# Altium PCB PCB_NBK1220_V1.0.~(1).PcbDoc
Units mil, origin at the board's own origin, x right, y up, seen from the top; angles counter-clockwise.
Board outline 2760.94 x 3491.25 mil, 2 copper layers (Top Layer, Bottom Layer), stack 21 mil thick; 40 components, 63 nets, 291 pads, 55 vias.
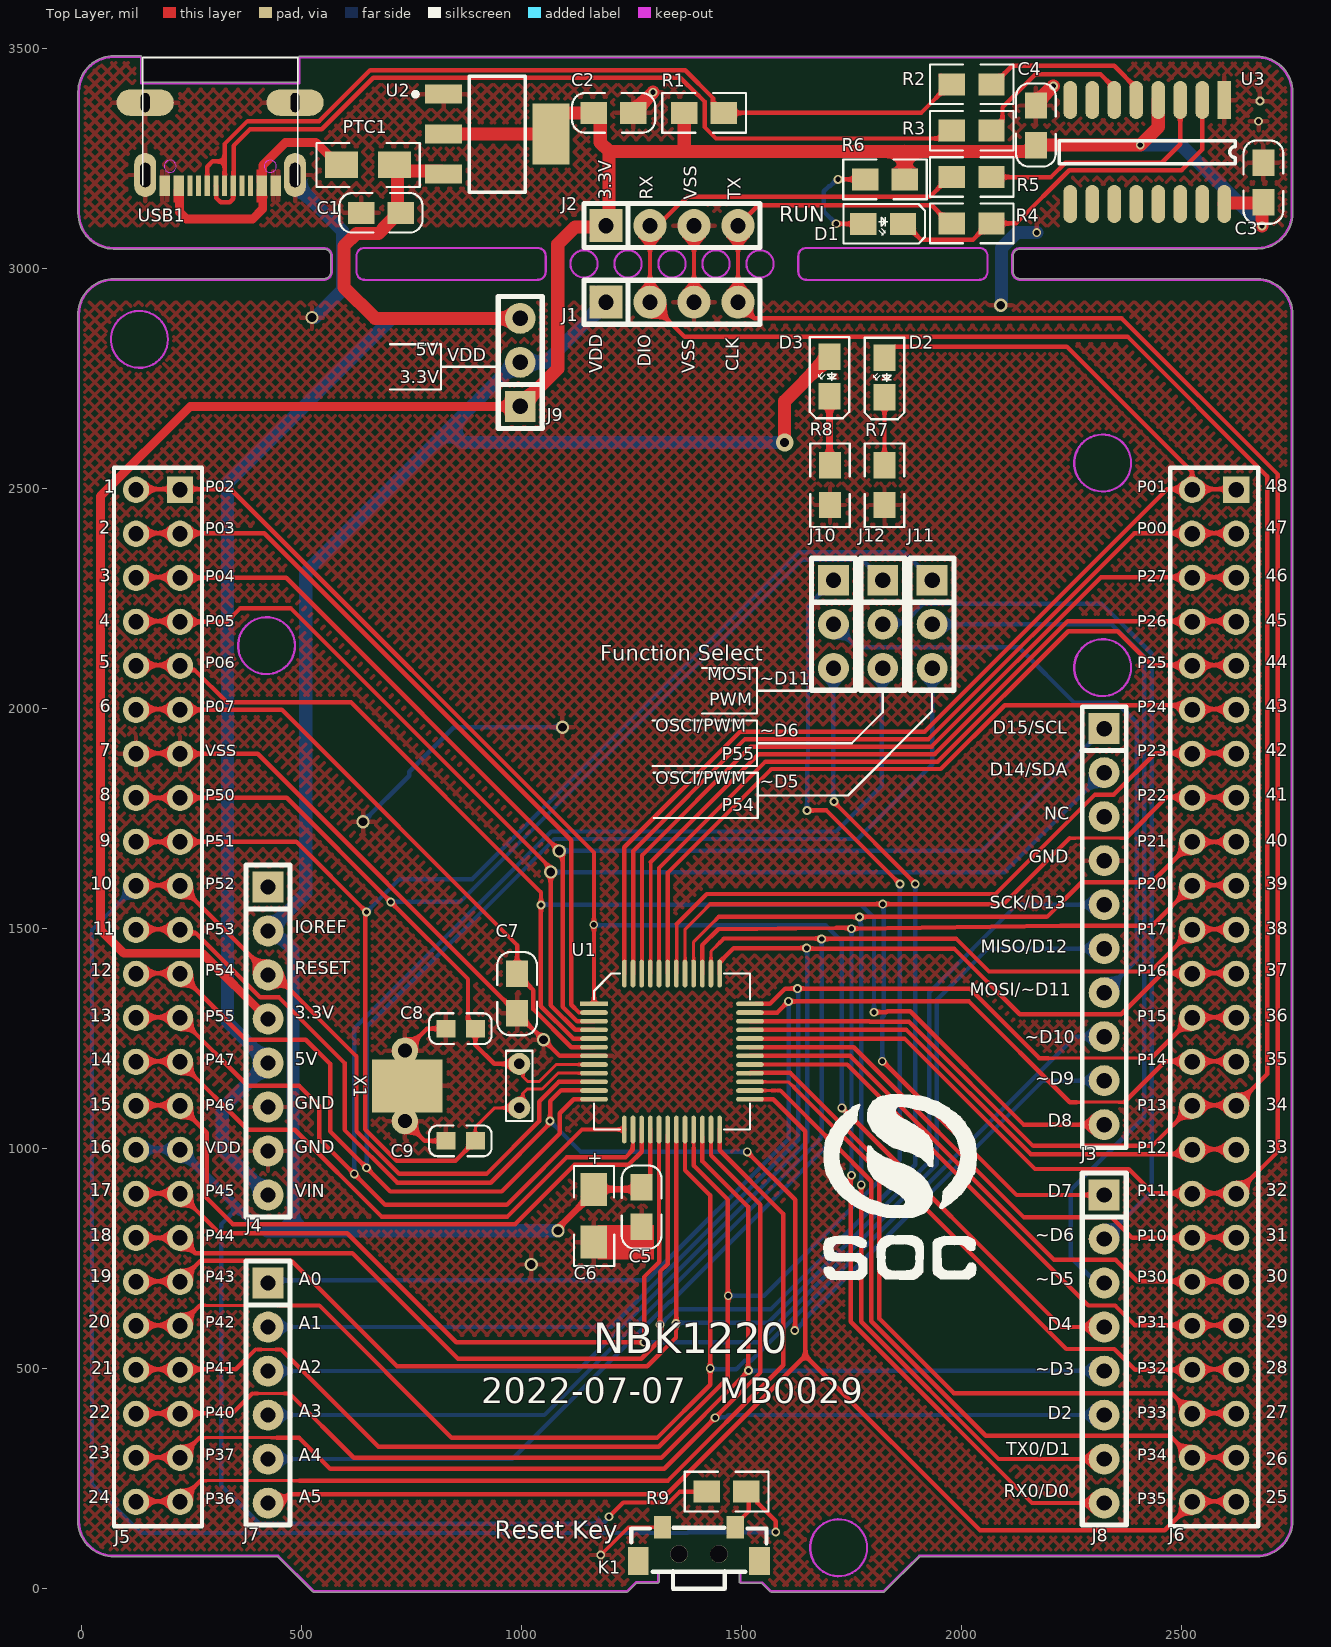
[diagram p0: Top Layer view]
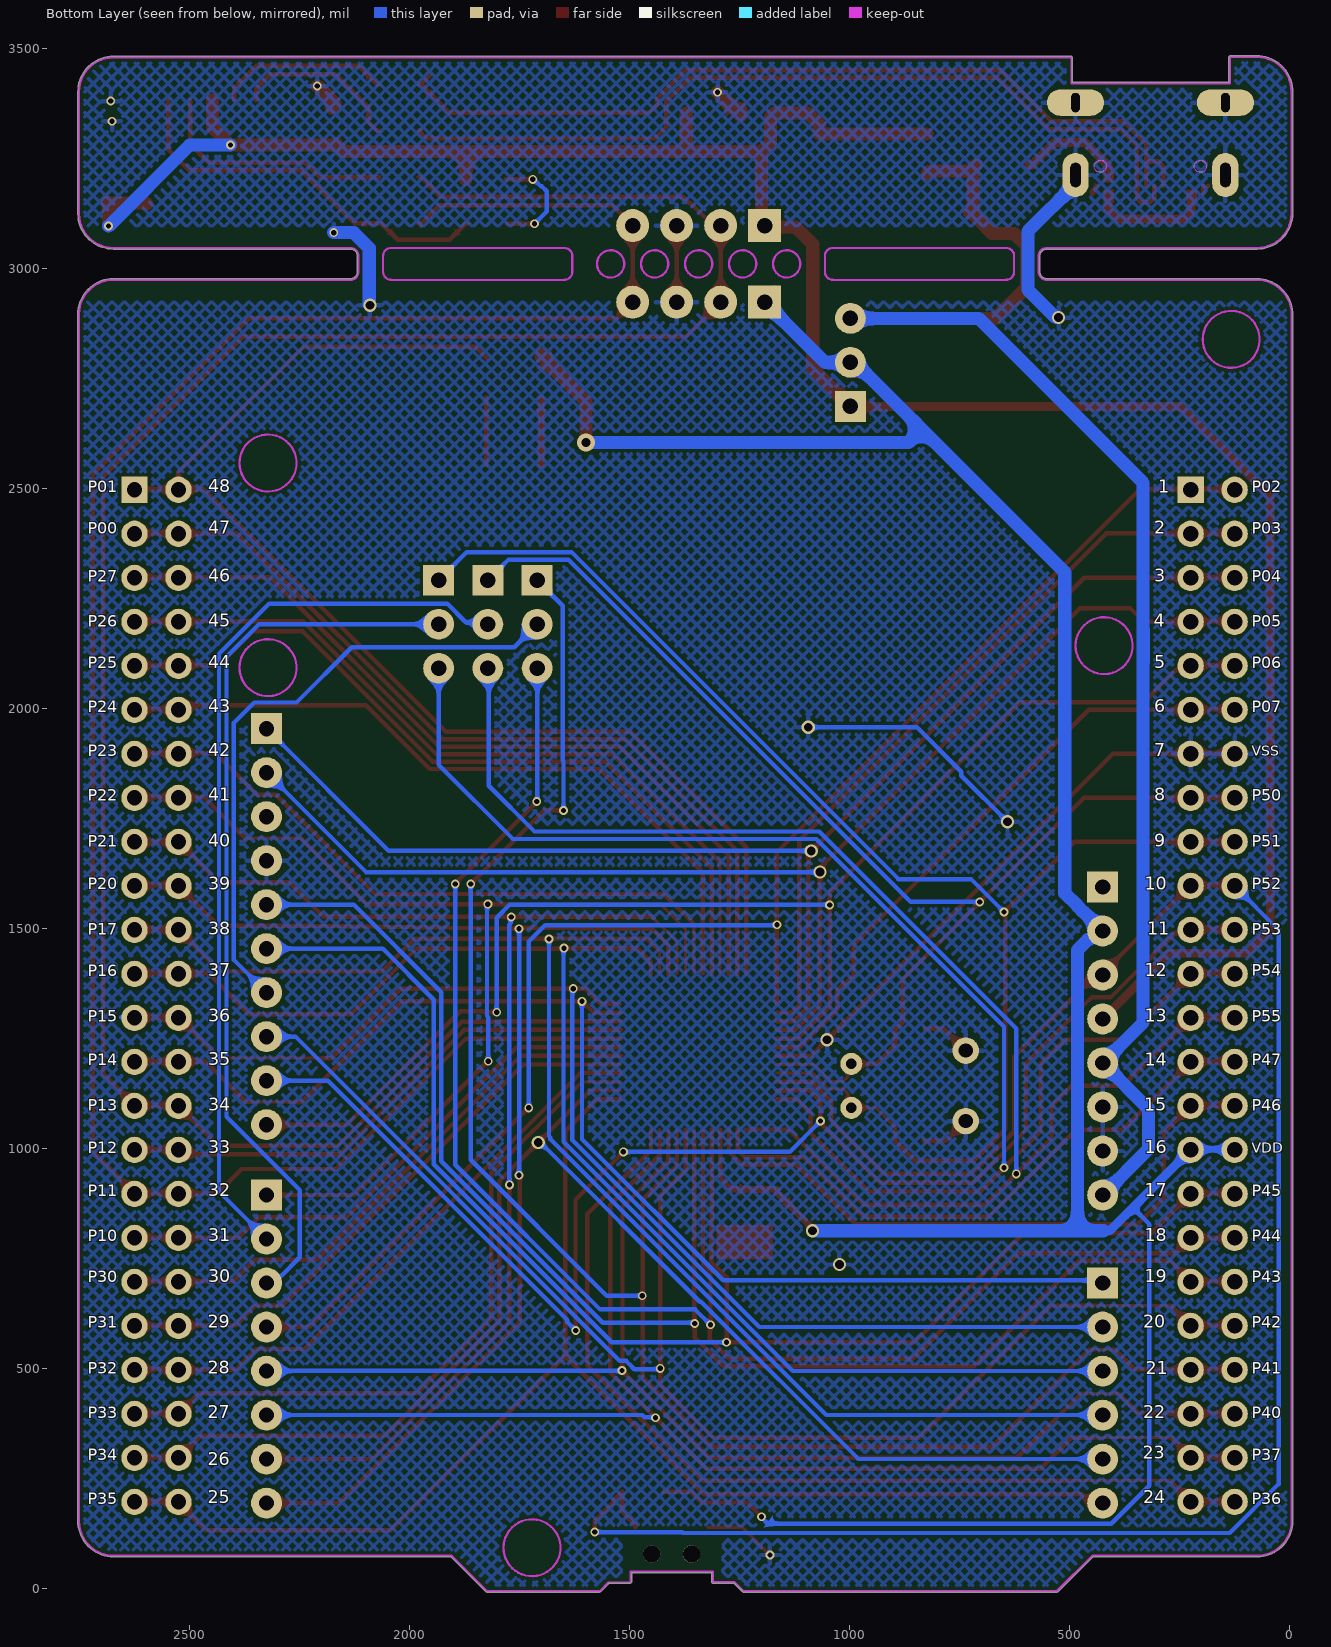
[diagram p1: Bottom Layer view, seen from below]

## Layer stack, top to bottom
Top Solder: solder mask 0.4, Solder Resist, Dk 3.5
Top Layer: signal copper 1.4
Dielectric 1: prepreg 2.8, PP-006, Dk 4.1
Dielectric1: dielectric 12.6, FR-4, Dk 4.8
Dielectric 2: prepreg 2.8, PP-006, Dk 4.1
Bottom Layer: signal copper 1.4
Bottom Solder: solder mask 0.4, Solder Resist, Dk 3.5

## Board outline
73.06,71.8 446.03,71.8 525.62,-7.79 527.39,-8.52 1240.4,-8.52 1242.18,-7.78 1261.44,11.48 1310,11.48 1312.51,14 1312.51,35.49 1494.49,35.49 1494.49,13.73 1497.36,11.21 1545.92,11.21 1565.18,-8.05 1568.1,-8.52 1823.45,-8.52 1825.23,-7.78 1904.81,71.8 2671.48,71.8 ccw(c2671.48,153.06) 2752.74,153.05 2752.74,2895.58 ccw(c2672.03,2895.58) 2672.58,2976.28 2671.95,2976.37 2133.15,2976.37 cw(c2133.15,2992) 2117.51,2992 2117.51,3028 cw(c2133.15,3028) 2133.15,3043.63 2671.95,3043.63 ccw(c2671.95,3124.34) 2752.66,3124.34 2752.66,3400.93 ccw(c2671.95,3400.93) 2671.95,3481.64 495,3481.64 492.49,3479.12 492.49,3422.52 137.51,3422.52 137.51,3480 134.78,3482.74 73.35,3482.74 ccw(c73.35,3401.48) -7.91,3401.48 -7.91,3124.89 ccw(c73.35,3124.89) 73.22,3043.63 550.95,3043.63 cw(c550.95,3028) 566.59,3028 566.59,2992 cw(c550.95,2992) 550.95,2976.37 550.06,2976.2 73.06,2976.2 ccw(c73.05,2894.94) -8.03,2900.23 -8.2,2899.31 -8.2,154 -8.2,153.05 ccw(c73.06,153.05)

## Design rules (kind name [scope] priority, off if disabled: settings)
Clearance Clearance_2 [(InComponent('U1') AND IsPad)] p1: gap=6 ignorepadtopadclearanceinfootprint=FALSE except(0: Arc-Hole Track-Hole SMDPad-Hole THPad-Hole Via-Hole Fill-Hole Poly-Hole Region-Hole Text-Hole)
Clearance Clearance_1 [All] p2: gap=6 ignorepadtopadclearanceinfootprint=FALSE except(0: Arc-Hole Track-Hole SMDPad-Hole THPad-Hole Via-Hole Fill-Hole Poly-Hole Region-Hole Text-Hole)
ComponentClearance [All] p1 off: gap=10 collisioncheckmode=3 verticalgap=10 showdistances=FALSE
Height [All] p1 off: minheight=0 maxheight=1000 prefheight=500
HoleSize [All] p1: absolutevalues=TRUE maxlimit=150 minlimit=1 maxpercent=80.000 minpercent=20.000
MinimumSolderMaskSliver [All] p1: minsoldermaskwidth=0
PolygonConnect [All] p1: connectstyle=Relief reliefconductorwidth=10 reliefentries=4 polygonreliefangle="90 Angle" airgapwidth=10
RoutingVias [All] p1: holewidth=28 width=50 viastyle="Through Hole" minholewidth=10 minwidth=20 maxholewidth=130 maxwidth=180
SilkToSilkClearance [All] p1 off: silktosilkclearance=0
SilkToSolderMaskClearance [IsPad] p1 off: minsilkscreentomaskgap=0 clearancetoexposedcopper=TRUE
SolderMaskExpansion [All] p1: expansion=4 istentingtop=FALSE
Width [All] p1: maxlimit=30 minlimit=5 preferedwidth=7
24 further rules are at their usual default settings.

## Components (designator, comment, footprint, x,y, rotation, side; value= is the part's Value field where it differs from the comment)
C1 "104" C0805 726,3126 r180 top
C2 "104" C0805 1164,3353 r0 top
C3 "104" C0805 2686,3150.2 r90 top
C4 "104" C0805 2169,3280 r90 top
C5 "104" C0805 1273,912 r270 top
C6 "10uF" A-3216 1164,907 r270 top
C7 "103" C0805 990,1397 r270 top
C8 "10pF" C0603 895,1272 r180 top
C9 "10pF" C0603 895,1017 r180 top
D1 "LED-Bule" LED0805 1822,3101 r0 top
D2 "LED-Bule" LED0805 1825,2752 r270 top
D3 "LED-Yellow" LED0805 1700,2754 r270 top
J1 "CON1*4" CON1*4(P=2.54) 1342,2923 r0 top
J2 "CON1*4" CON1*4(P=2.54) 1342,3097 r0 top
J3 "CON1*10" CON1*10(P=2.54) 2324,1504 r270 top
J4 "CON1*8" CON1*8(P=2.54) 424,1244 r270 top
J5 "CON2*24" CON2*24(P=2.54) 189,1346.5 r270 top
J6 "CON2*24" CON2*24(P=2.54) 2589,1346.5 r270 top
J7 "CON1*6" CON1*6(P=2.54) 424,444 r270 top
J8 "CON1*8" CON1*8(P=2.54) 2324,544 r270 top
J9 "CON1*3" CON1*3(P=2.54) 997,2786 r90 top
J10 "CON1*3" CON1*3(P=2.54) 1709,2191 r270 top
J11 "CON1*3" CON1*3(P=2.54) 1933,2191 r270 top
J12 "CON1*3" CON1*3(P=2.54) 1821,2191 r270 top
K1 "单路开关" SW-SMD_UK-B0246-SP25Y 1403.28,100.64 r180 top
PTC1 "0.5A 6V 自恢复保险丝" R1206 591,3235 r0 top
R1 "1.5K" R0805 1370,3353 r0 top
R2 "22R" R0805 1978,3418 r0 top
R3 "22R" R0805 1978,3312.67 r0 top
R4 "100R" R0805 2068,3102 r180 top
R5 "100R" R0805 2068,3207.33 r180 top
R6 "2.2K" R0805 1871,3202 r180 top
R7 "5.1K" R0805 1825,2552 r270 top
R8 "5.1K" R0805 1701,2552 r270 top
R9 "1.5K" R0805 1511,220 r180 top
U1 "SC95F8617B" LQFP-48(7X7) 1342,1220 r0 top
U2 "AMS1117-3.3V" SOT-223 945,3305 r270 top
U3 "CH340C" SOP16 2597,3382.22 r270 top
USB1 "TYPE-C" TYPE-C1 315.22,3282.01 r0 top
X1 "32.768K" 32768 995,1192 r270 top

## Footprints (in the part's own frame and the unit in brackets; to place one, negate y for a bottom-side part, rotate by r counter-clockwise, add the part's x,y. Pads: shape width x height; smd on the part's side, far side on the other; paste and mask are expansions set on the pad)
32768 [mil] "32.768KHZ"
  round 60 hole 32: 0(-30,-260) 0(130,-260)
  rect 120x160 smd: 0(50,-255)
  round 50 hole 24: 1(0,0) 2(100,0)
  silkscreen extent -30,-30 130,30
A-3216 [mil]
  rect 75x60 smd: 1(0,0) 2(120,0)
  silkscreen extent -53,-45 174,47
C0603 [mm]
  rect 1.1x1 smd: 1(0,0) 2(1.7,0)
  silkscreen extent -0.94,-0.89 2.67,0.89
C0805 [mil]
  rect 60x50 smd: 1(0,0) 2(90,0)
  silkscreen extent -49,-45 140,45
CON1*3(P=2.54) [mil]
  rect 70x70 hole 35: 1(-100,0)
  round 70 hole 35: 2(0,0) 3(100,0)
  silkscreen extent -150,-50 150,50
CON1*4(P=2.54) [mil]
  rect 75x75 hole 35: 1(-150,0)
  round 75 hole 35: 2(-50,0) 3(50,0) 4(150,0)
  silkscreen extent -200,-50 200,50
CON1*6(P=2.54) [mil]
  rect 70x70 hole 35: 1(-250,0)
  round 70 hole 35: 2(-150,0) 3(-50,0) 4(50,0) 5(150,0) 6(250,0)
  silkscreen extent -300,-50 300,50
CON1*8(P=2.54) [mil]
  rect 70x70 hole 35: 1(-350,0)
  round 70 hole 35: 2(-250,0) 3(-150,0) 4(-50,0) 5(50,0) 6(150,0) 7(250,0) 8(350,0)
  silkscreen extent -400,-50 400,50
CON1*10(P=2.54) [mil]
  rect 70x70 hole 35: 1(-450,0)
  round 70 hole 35: 2(-350,0) 3(-250,0) 4(-150,0) 5(-50,0) 6(50,0) 7(150,0) 8(250,0) 9(350,0) 10(450,0)
  silkscreen extent -500,-50 502,50
CON2*24(P=2.54) [mil]
  rect 60x60 hole 35: 1(-1150,35)
  round 60 hole 35: 2(-1150,-65) 3(-1050,35) 4(-1050,-65) 5(-950,35) 6(-950,-65) 7(-850,35) 8(-850,-65) 9(-750,35) 10(-750,-65) 11(-650,35) 12(-650,-65) 13(-550,35) 14(-550,-65) 15(-450,35) 16(-450,-65) 17(-350,35) 18(-350,-65) 19(-250,35) 20(-250,-65) 21(-150,35) 22(-150,-65) 23(-50,35) 24(-50,-65) 25(50,35) 26(50,-65) 27(150,35) 28(150,-65) 29(250,35) 30(250,-65) 31(350,35) 32(350,-65) 33(450,35) 34(450,-65) 35(550,35) 36(550,-65) 37(650,35) 38(650,-65) 39(750,35) 40(750,-65) 41(850,35) 42(850,-65) 43(950,35) 44(950,-65) 45(1050,35) 46(1050,-65) 47(1150,35) 48(1150,-65)
  silkscreen extent -1200,-115 1205,85
LED0805 [mil]
  rect 60x50 smd: 1(-45,0) 2(45,0)
  silkscreen extent -90,-45 95,45
LQFP-48(7X7) [mm]
  rect 1.6x0.27 smd: 1(-4.5,2.75)
  oval 1.6x0.27 smd: 2(-4.5,2.25) 3(-4.5,1.75) 4(-4.5,1.25) 5(-4.5,0.75) 6(-4.5,0.25) 7(-4.5,-0.25) 8(-4.5,-0.75) 9(-4.5,-1.25) 10(-4.5,-1.75) 11(-4.5,-2.25) 12(-4.5,-2.75) 25(4.5,-2.75) 26(4.5,-2.25) 27(4.5,-1.75) 28(4.5,-1.25) 29(4.5,-0.75) 30(4.5,-0.25) 31(4.5,0.25) 32(4.5,0.75) 33(4.5,1.25) 34(4.5,1.75) 35(4.5,2.25) 36(4.5,2.75)
  oval 0.27x1.6 smd: 13(-2.75,-4.5) 14(-2.25,-4.5) 15(-1.75,-4.5) 16(-1.25,-4.5) 17(-0.75,-4.5) 18(-0.25,-4.5) 19(0.25,-4.5) 20(0.75,-4.5) 21(1.25,-4.5) 22(1.75,-4.5) 23(2.25,-4.5) 24(2.75,-4.5) 37(2.75,4.5) 38(2.25,4.5) 39(1.75,4.5) 40(1.25,4.5) 41(0.75,4.5) 42(0.25,4.5) 43(-0.25,4.5) 44(-0.75,4.5) 45(-1.25,4.5) 46(-1.75,4.5) 47(-2.25,4.5) 48(-2.75,4.5)
  silkscreen extent -4.5,-4.5 4.5,4.5
R0805 [mil]
  rect 60x50 smd: 1(0,0) 2(90,0)
  silkscreen extent -50,-45 140,45
R1206 [mil]
  rect 75x60 smd: 1(0,0) 2(120,0)
  silkscreen extent -57,-50 178,50
SOP16 [mm]
  rect 2.2x0.8 smd: 1(0,0)
  oval 2.2x0.8 smd: 2(0,-1.27) 3(0,-2.54) 4(0,-3.81) 5(0,-5.08) 6(0,-6.35) 7(0,-7.62) 8(0,-8.89) 9(6,-8.89) 10(6,-7.62) 11(6,-6.35) 12(6,-5.08) 13(6,-3.81) 14(6,-2.54) 15(6,-1.27) 16(6,0)
  silkscreen extent 2.33,-9.53 3.67,0.64
SOT-223 [mm]
  rect 1.1x2.15 smd: 1(-2.3,-3.1) 2(0,-3.1) 3(2.3,-3.1)
  rect 3.5x2.15 smd: 2(0,3.1)
  silkscreen extent -3.35,-4.85 3.35,1.63
SW-SMD_UK-B0246-SP25Y [mm]
  rect 1x1.3 smd: 1(2.1,-0.975) 2(-2.1,-0.975)
  rect 1.2x1.6 smd: 3(-3.5,0.975) 4(3.5,0.975)
  round 1 hole 1 unplated: ""(-1.15,0.575) ""(1.15,0.575)
  silkscreen extent -3.9,-0.95 3.9,2.57
TYPE-C1 [mm]
  oval 3.302x1.524 / inner oval 1.27x2.54 / far side oval 3.302x1.524 hole 0.5 slot 1.1 at 90 deg: 1(-4.325,2.4) 3(4.325,2.4)
  oval 1.27x2.54 / inner oval 1.27x2.54 / far side oval 1.524x2.54 hole 0.6 slot 1.4 at 90 deg: 2(-4.325,-1.78) 4(4.325,-1.78)
  rect 0.3x1.2 smd: A1(3.355,-2.4) A4(2.555,-2.4) A5(1.255,-2.4) A6(0.255,-2.4) A7(-0.245,-2.4) A8(-1.245,-2.4) A9(-2.545,-2.4) A12(-3.345,-2.4) B1(-3.045,-2.4) B4(-2.245,-2.4) B5(-1.745,-2.4) B6(-0.745,-2.4) B7(0.755,-2.4) B8(1.755,-2.4) B9(2.255,-2.4) B12(3.055,-2.4)
  Keep-Out Layer circle w0.05: c-2.885,-1.28 r0.35
  Keep-Out Layer circle w0.05: c2.895,-1.28 r0.35
  silkscreen extent -4.47,-2.35 4.48,5

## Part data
C1 C2 C3 C4 C5 C7 C8 C9: library part CAP1, "贴片电容"
C6: library part T-A/4.7uF/16V
D1 D2: library part LED-CP, "蓝色"
D3: library part LED-CP, "黄色"
K1: library part KEY-6
PTC1: library part PTC-MZ11-06A200-400RM, "6V 500mA PTC自恢复保险丝"
R1 R2 R3 R4 R5 R6 R7 R8 R9: library part R0805
U1: "电压:2.0V-5.5V;ROM:128KB;RAM:内部256B+外部8KB+ PWM&LCD 80B;32/16/8/4MHz"
U2: library part LDO-SPX1117M3, "LDO；1A；SOT-223-3"
USB1: library part TYPE-C1, "Type-c母座16pin 快充闪充usb3.0沉板母座连接器"
X1: library part CRYSTAL

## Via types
v1: diameter 20, hole 12, Top Layer to Bottom Layer, 44 vias
v2: diameter 30, hole 20, Top Layer to Bottom Layer, tented both sides, 8 vias
v3: diameter 30, hole 20, Top Layer to Bottom Layer, 2 vias
v4: diameter 40, hole 20, Top Layer to Bottom Layer, tented both sides, 1 vias

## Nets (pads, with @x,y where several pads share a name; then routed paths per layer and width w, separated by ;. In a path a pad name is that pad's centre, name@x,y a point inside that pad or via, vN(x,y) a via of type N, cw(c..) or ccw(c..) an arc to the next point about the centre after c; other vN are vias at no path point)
3.3V: C2.1 C3.1 C4.1 J2.1 J4.4 J9.1 R1.1 R6.1 U2.2 U3.4 U3.16 | length 5682
  Top Layer w20: J4.4 274.5,1443.5 96.5,1443.5 43,1497 43,2481.97 247.03,2686 J9.1
  Top Layer w30: U2.2@822.95,3305 1067.05,3305 1067.05,3325.68 1094.37,3353 C2.1 1169,3353 1179,3343 1179,3285.67 1199,3265.67 ; J9.1 1082.5,2771.5 1082.5,3054.5 1122,3094 1189,3094 J2.1 1199,3104 1199,3265.67 ; R1.1 1370,3265.67 ; R6.1 1871,3265.67 ; C4.1@2165,3280 v1(2406,3280) 2447,3321 U3.4 ; C4.1@2165,3282 2148.67,3265.67 1871,3265.67 ; U3.16 2597,3147.41 2597.69,3148.1 C3.1@2683.9,3148.1 ; v1(2683,3096) 2683,3147.2 C3.1@2683.9,3148.1 ; C3.1 C3.1@2683.9,3148.1 ; 1199,3265.67 1370,3265.67 ; 1370,3265.67 1871,3265.67
  Bottom Layer w30: J2.1@1169.5,3074.5 J2.1 ; v1(2406,3280) 2499,3280 v1(2683,3096)
5V: C1.1 J4.5 J4.8 J9.3 PTC1.2 U2.3 | length 3483.2
  Top Layer w30: U2.3 816.3,3221.1 724.9,3221.1 PTC1.2 718.5,3227.5 718.5,3133.5 C1.1 721,3126 688,3093 688,3091.89 675.06,3078.94 624.94,3078.94 596.6,3050.6 596.6,2957 667.6,2886 J9.3
  Bottom Layer w30: J4.8 320,998 320,1090 J4.5 332,1286 332,2104.95 331.48,2105.47 331.48,2179.38 332,2179.9 332,2512.33 705.67,2886 J9.3
A0: J6.27 J6.28 J7.1 U1.35 | length 2886.2
  Top Layer w7: 2262,1105 2369.87,1105
  Top Layer w10: U1.35 1581.06,1308.58 1606.48,1334 2016.89,1334 2245.89,1105 2262,1105 ; 2369.87,1105 2462.87,1198 2524,1198 J6.27@2624,1198
  Bottom Layer w10: J7.1 430,700 1286,700 1607,1021 v1(1607,1334) ; J6.27@2624,1192 J6.27@2624,1198
A1: J6.25 J6.26 J7.2 U1.36 | length 2979.1
  Top Layer w7: U1.36 U1.36@1533,1328.27 ; 2197,1205 2431,1205
  Top Layer w10: U1.36@1533,1328.27 1564.27,1328.27 1599,1363 v1(1627,1363) 2019,1363 2177,1205 2197,1205 ; 2431,1205 2524,1298 J6.25@2624,1298
  Bottom Layer w10: J7.2 1204.04,594 1629,1018.96 1629,1343.11 1628.91,1343.2 1628.91,1361.09 v1(1627,1363) ; J6.25@2624,1298 2654,1298
A2: J6.23 J6.24 J7.3 U1.37 | length 3208.4
  Top Layer w10: J7.3 J7.3@433.77,484.23 ; U1.37 1450.27,1423.35 1481.92,1455 v1(1648,1455) ; v1@1648,1454 1983,1454 2132,1305 2363,1305 2456,1398 J6.23@2624,1398
  Bottom Layer w10: J7.3 1128.08,494 1649,1014.92 1649,1454 v1(1648,1455)
A3: J6.21 J6.22 J7.4 U1.38 | length 3300.3
  Top Layer w7: U1.38 1430.58,1447.58 1449.91,1466.91
  Top Layer w10: J7.4@421,394 J7.4 ; 1449.91,1466.91 1460,1477 1681,1477 v1(1682,1476) 1988.29,1476 2062.29,1402 2429.5,1402 J6.22 ; J6.22@2524,1498 J6.21@2624,1498
  Bottom Layer w10: J7.4 1052.12,394 1679.26,1021.14 1679.26,1024.7 1682,1027.44 v1(1682,1476)
A4: J6.45 J6.46 J7.5 U1.26 | length 3216.6
  Top Layer w7: U1.26 1581.58,1131.42
  Top Layer w10: 1581.58,1131.42 1588.36,1131.42 v2(1706.26,1013.51) ; v2@1710,1014.62 1710,1010.23 1795,925.23 1795,607.08 2055.08,347 2473.5,347 J6.46 ; J6.46@2524,298 J6.45@2624,298
  Bottom Layer w10: J7.5 978.89,294 1336.56,651.68 1339.68,651.68 1701.51,1013.51 v2(1706.26,1013.51)
A5: J6.47 J6.48 J7.6 U1.25 | length 3198.8
  Top Layer w10: J7.6 451.7,194 471.7,214 1330,214 1645,529 ; U1.25 1572.27,1111.73 1645,1039 1645,529 ; J6.47@2624,198 2524,198 2524,194 2462,132 2042,132 1645,529
CLK: J1.4 J2.4 J6.33 J6.34 R4.2 U1.32 | length 5015.4
  Top Layer w10: U1.32 1870.43,1249.53 2166.96,953 2380,953 2435,898 2624,898 2719,993 2719,2531.28 2364.28,2886 1529.25,2886 1492.25,2923 J1.4 J2.4 1538,3143 1932,3143 1973,3102 R4.2 R4.2@1973,3097
CMOD: C7.1 J5.11 J5.12 U1.6 | length 1423.6
  Top Layer w10: J5.12@124,1998 J5.11@224,1998 ; J5.11 455.5,1996.5 990,1462 C7.1 ; C7.1@990,1396.08 990,1392 1010,1372 1014.08,1372 1027,1359.08 1027,1316.15 1113.31,1229.84 U1.6
D2: J5.45 J5.46 J8.6 U1.23 | length 3056.1
  Top Layer w7: 268.5,342.5 444.09,342.5 ; U1.23@1430.58,1013.63 U1.23
  Top Layer w10: J5.46@124,298 224,298 268.5,342.5 ; 444.09,342.5 494.5,342.5 565,272 1324.11,272 v1(1440.06,387.94) ; U1.23@1430.58,1013.63 1430.58,984.42 1543,872 1543,490.89 1443.11,391 v1@1437,391
  Bottom Layer w10: J5.45@224,286 J5.45@224,298 ; v1(1440.06,387.94) 1441.11,389 1465.06,389 1470.06,394 J8.6
D4: J5.1 J5.2 J8.4 U1.1 | length 3487.3
  Top Layer w10: J5.2@124,2498 224,2498 339.23,2498 1164.83,1672.39 v1@1164.83,1508 ; v1(1164,1508) 1164.83,1507.16 U1.1 ; v1(1728,1092) 1729,1092 2227,594 J8.4
  Bottom Layer w10: v1(1164,1508) 1165,1507 1691,1507 1728,1470 v1(1728,1092)
D7: J6.15 J6.16 J8.1 U1.41 | length 2478.4
  Top Layer w7: U1.41@1371.8,1397.17 1371.8,1498.13 1428.67,1555 ; 2245.58,1705 2373,1705
  Top Layer w10: 1428.67,1555 2095.58,1555 2245.58,1705 ; v1(1820,1198) 1821,1198 2125,894 J8.1 ; 2373,1705 2466,1798 J6.15@2624,1798
  Bottom Layer w10: v1(1820,1198) 1820,1297.89 1823,1300.89 1823,1550.29 1821,1552.29 v1(1821,1555) ; J6.16@2524,1786 J6.16 J6.16@2524,1798
D8: J3.10 J5.9 J5.10 U1.5 | length 3177.2
  Top Layer w10: J5.10@124,2098 J5.9@224,2098 ; J5.9 233.57,2086.93 257.07,2086.93 330.5,2013.5 612.5,2013.5 1044.33,1581.67 v1(1044.33,1553) ; v1@1048.95,1553 1048.62,1553 1044,1548.38 1044,1323.2 1117.67,1249.53 U1.5 ; v1(1801,1309.5) 1829,1309.5 1831,1311.5 1883.5,1311.5 2141,1054 J3.10
  Bottom Layer w10: v1(1044.33,1553) 1045.33,1554 1771.11,1554 1801,1524.11 v1(1801,1309.5) ; J3.10@2312,1042 J3.10
D13: J6.31 J6.32 U1.33 | length 1225.7
  Top Layer w10: U1.33 1874.79,1269.21 2157,987 2514.5,987 J6.32 ; J6.32@2524,998 J6.31@2624,998
D+: R1.2 R2.1 USB1.A6 USB1.B6 | length 2008.3
  Top Layer w10: USB1.B6 285.89,3230.89 298,3243 325.26,3243 ; USB1.A6 325.26,3243 ; R2.1@1953,3438 R2.1@1973,3418 ; R2.1 R2.1@1973,3418 ; 325.26,3243 325.26,3282.3 377.45,3334.5 540.45,3334.5 655.96,3450 1372,3450 1435,3387 1435,3373 1455,3353 1908,3353 R2.1@1973,3418
D-: R3.1 USB1.A7 USB1.B7 | length 1994.6
  Top Layer w10: USB1.A7 306.48,3186.61 306.48,3159.8 316.28,3150 337,3150 344.94,3157.94 USB1.B7 345.85,3188.43 345.85,3278.85 383,3316 546,3316 663,3433 1361,3433 1400.26,3393.74 1401.24,3393.74 1416,3378.97 1416,3321 1442,3295 1960.33,3295 R3.1 R3.1@1973,3312.67
DIO: J1.2 J2.2 J6.29 J6.30 R5.2 U1.34 | length 5191.1
  Top Layer w10: U1.34 1790.49,1288.9 1791.89,1287.5 1880.54,1287.5 2162.54,1005.5 2433,1005.5 J6.30 ; R5.2 1973,3207.33 1927.78,3162.11 1376.89,3162.11 1362.91,3148.13 1360.67,3148.13 1309.54,3097 J2.2 J1.2 1371,2844 2378,2844 2695,2527 2695,1169 2624,1098 J6.30@2524,1098
GND: C1.2 C2.2 C3.2 C4.2 C5.2 C6.2 C7.2 C8.2 C9.2 J1.3 J2.3 J3.4 J4.6 J4.7 J5.13 J5.14 K1.1 R7.2 R8.2 U1.7 U2.1 U3.1 USB1.1 USB1.2 USB1.3 USB1.4 USB1.A1 USB1.A12 USB1.B1 USB1.B12 X1.0 | length 3288.6
  Top Layer w8: v1(1180,76) 1243.02,139.02 K1.1
  Top Layer w10: J5.14@124,1898 J5.13@224,1898 ; USB1.A12 USB1.A12@184.43,3186.61 ; USB1.B1@195.34,3169.8 USB1.B1 ; J5.13 400.5,1896.5 C7.2 v2(1050,1247) 1086.84,1210.16 U1.7 ; USB1.B12 447.56,3175.46 447.56,3169.55 USB1.A1@448.18,3168.9 ; X1.0@735,1062 780,1017 C9.2 C9.2@830,1017 ; X1.0@735,1222 785,1272 C8.2 ; J1.3 J2.3
  Top Layer w30: C2.2 C2.2@1253,3354 ; v1(1299,3400) C2.2@1253,3354 ; C4.2 2169,3375 C4.2@2176,3382 ; C4.2@2176,3365 C4.2@2176,3382 ; v1@2209.25,3414 2208,3414 C4.2@2176,3382 ; C2.2@1253,3354 1246,3347 1246,3361 C2.2@1253,3354
  Bottom Layer w10: v2(640,1742) 744.91,1846.91 744.91,1855.91 846,1957 v2(1093,1957)
  Bottom Layer w30: USB1.4 485.5,3191.93 593.6,3083.82 593.6,2951.6 530,2888 v3(524,2888) ; v3(2089,2916) 2090.5,2917.5 2090.5,3045.67 2125.83,3081 v1(2171,3081)
  other v1: 2675,3334 2678,3380 2208.63,3414
  other v2: 1022,736
IOREF: C5.1 C6.1 D3.1 J1.1 J4.2 J5.31 J5.32 J9.2 R9.2 U1.16 | length 6759.7
  Top Layer w10: v1(1199,163) 1231.33,195.33 1335.37,195.33 1360.04,220 R9.2 ; C5.1@1272,912 1292,932 1292,942.07 1292.79,942.86 U1.16
  Top Layer w15: v2(1083,813) 1085.87,815.87 1085.87,821.37 1164,899.5 C6.1 1267,907 C5.1@1272,912
  Top Layer w30: v4(1598,2604) 1598,2698 D3.1@1684,2784 ; D3.1 D3.1@1700,2804
  Bottom Layer w10: 355.25,865.25 318,828 318,233.53 404.53,147 1184.72,147 1199,161.28 v1(1199,163)
  Bottom Layer w15: J5.32@124,998 224,998 J5.31
  Bottom Layer w20: J5.31 355.25,865.25 407.85,812.65 422,812.65
  Bottom Layer w30: 422,812.65 481,812.65 ; v2(1083,813) 1082.65,812.65 481,812.65 ; J1.1@1169.5,2945.5 J1.1 1055,2786 J9.2 987,2786 835,2634 ; v4(1598,2604) 865,2604 835,2634 ; 481,812.65 481,1451 457.57,1474.43 454.39,1474.43 434.82,1494 J4.2 467,1537 468.11,1537 481,1549.89 481,1551 509.91,1579.91 509.91,2308.91 835,2634
MISO: J3.6 J5.33 J5.34 U1.17 | length 3429.3
  Top Layer w10: J5.34@124,898 224,898 224.75,897.25 J5.33 313.5,807 604,807 851.56,559.44 v1(1278.56,559.44) 1278.56,707.59 1313,742.03 1313,830.97 1312.47,831.5 U1.17
  Bottom Layer w10: v1(1278.56,559.44) 1539.53,559.44 1944,963.92 1944,1338 2060,1454 J3.6
MOSI: J5.35 J5.36 J10.3 U1.18 | length 3767.5
  Top Layer w7: U1.18@1332.16,1031 U1.18
  Top Layer w10: J5.36 J5.35 258.5,762 615.61,762 855.61,522 1272.23,522 1316.56,566.33 1316.56,597.44 v1(1315,599) 1315,719.99 1332.16,737.15 U1.18@1332.16,1031 ; v1(1710,1788) 1710,1787 1895,1602 v1(1895,1601)
  Bottom Layer w10: J5.35 J5.35@238.5,782 ; v1(1315,599) 1350,634 1566,634 1895,963 v1(1895,1601) ; v1@1708.5,1785.5 1708.5,2090.5 J10.3
NetD1_1: D1.1 R6.2 | length 252.8
  Top Layer w10: v1(1715,3101) D1.1 ; v1(1719,3202) R6.2
  Bottom Layer w10: v1(1715,3101) 1687,3129 1687,3175 1697.94,3185.94 1700.24,3185.94 1716.29,3202 v1(1719,3202)
NetD2_2: D2.2 R7.1 | length 155
  Top Layer w10: R7.1 D2.2
NetD3_2: D3.2 R8.1 | length 152.4
  Top Layer w15: D3.2@1700,2704 1700,2553 R8.1
P00: J6.3 J6.4 U1.47 | length 1948
  Top Layer w10: U1.47@1253.73,1397.17 1253.8,1397.23 1253.8,1675.8 1508,1930 1924.83,1930 2392.83,2398 2524,2398 J6.3@2624,2398
P01: D2.1 J6.1 J6.2 U1.48 | length 2882.2
  Top Layer w10: U1.48 1233.73,1684.02 1496.72,1947 1916,1947 2467,2498 J6.2@2524,2498 ; D2.1 1850,2822 2239,2822 2524,2537 J6.2@2524,2498 ; J6.2 J6.2@2524,2498 ; J6.1@2624,2498 J6.2@2524,2498
P03: J5.3 J5.4 U1.2 | length 1711.1
  Top Layer w10: J5.4@124,2398 224,2398 415.18,2398 1113,1700.18 1113,1326.32 1130.62,1308.7 1164.71,1308.7 U1.2
P10: J6.35 J6.36 U1.31 | length 1284.3
  Top Layer w10: U1.31 1755.16,1229.84 2142,843 2341.47,843 2387.97,796.5 J6.36 ; J6.36@2524,798 J6.35@2624,798
P23: J6.13 J6.14 U1.42 | length 1543.6
  Top Layer w7: U1.42@1352.8,1398.17 1352.8,1509.8
  Top Layer w10: 1352.8,1509.8 1421,1578 2077.29,1578 2303.29,1804 2346,1804 2440,1898 J6.13@2624,1898
P24: J6.11 J6.12 U1.43 | length 1681
  Top Layer w10: U1.43@1332.8,1398.17 1332.8,1626.8 1568,1862 1953,1862 2098,2007 2515,2007 2524,1998 J6.11@2624,1998
P25: J6.9 J6.10 U1.44 | length 1806.5
  Top Layer w10: U1.44 1312.47,1637.1 1554.37,1879 1945.96,1879 2242.31,2175.35 2355.04,2175.35 2432.39,2098 2524,2098 J6.9@2624,2098
P26: J6.7 J6.8 U1.45 | length 1810.5
  Top Layer w7: U1.45@1293.8,1397.17 1293.8,1650.8
  Top Layer w10: 1293.8,1650.8 1539,1896 1938.92,1896 2240.92,2198 2524,2198 J6.7@2624,2198
P27: J6.5 J6.6 U1.46 | length 1880.7
  Top Layer w10: U1.46@1273.8,1397.17 1273.8,1665.8 1521,1913 1931.88,1913 2316.88,2298 2524,2298 J6.5@2624,2298
P30: J6.37 J6.38 U1.30 | length 1317
  Top Layer w10: U1.30 1746.84,1210.16 2210,747 2350,747 2399,698 2524,698 J6.37@2624,698
P31: J6.39 J6.40 U1.29 | length 1350.2
  Top Layer w7: U1.29 U1.29@1531,1190.47
  Top Layer w10: U1.29@1531,1190.47 1740.53,1190.47 2288,643 2349,643 2394,598 J6.39@2624,598
P32: J6.41 J6.42 U1.28 | length 1384.7
  Top Layer w10: U1.28 1519.85,1171.47 1610.53,1171.47 2238,544 2347.13,544 2394.63,496.5 J6.42 ; J6.42@2524,498 J6.41@2624,498
P33: J6.43 J6.44 U1.27 | length 1611.8
  Top Layer w7: U1.27 1606.86,1151.1 1618.38,1139.58
  Top Layer w10: 1618.38,1139.58 1813,944.96 1813,613.12 1982.59,443.53 2476.97,443.53 J6.44 ; J6.44@2524,398 J6.43@2624,398
P36: J5.47 J5.48 U1.24 | length 2194.8
  Top Layer w7: 271,245 495,245
  Top Layer w10: J5.48@124,198 224,198 271,245 ; 495,245 1333,245 1595,507 1595,851 1450.27,995.73 U1.24
P46: J5.29 J5.30 U1.15 | length 1466
  Top Layer w10: J5.30@124,1098 J5.29@224,1098 ; J5.29 285,1035.5 285,887 344,828 986,828 1120.5,962.5 1243.42,962.5 1273.1,992.18 U1.15
P47: J5.27 J5.28 U1.14 | length 1410
  Top Layer w7: 1236.38,978 1237,978 1253.42,994.42 1253.42,996.54
  Top Layer w10: J5.28@124,1198 J5.27@224,1198 ; J5.27 378,1042.5 484.5,1042.5 682,845 968,845 1102.5,979.5 1236.38,979.5 1253.42,996.54 U1.14
P54: J5.23 J5.24 J11.3 U1.12 | length 3672.2
  Top Layer w10: J5.24@124,1398 224,1398 331.5,1290.5 ; J5.23 373.5,1247 510,1247 565,1192 565,1039 v1(648,956) 702,902 955.1,902 1087,1033.9 1087,1080 1118.73,1111.73 U1.12
  Bottom Layer w10: v1(648,956) 648,1276.18 1074.82,1703 1764,1703 1933,1872 J11.3
P55: J5.25 J5.26 J12.3 U1.13 | length 3426.3
  Top Layer w10: J5.26@124,1298 J5.25@224,1298 ; J5.25 378,1142.5 494.5,1142.5 540,1097 540,1022 v1(620,942) 690.5,871.5 966.22,871.5 1137.55,1042.83 U1.13
  Bottom Layer w10: v1(620,942) 620,1272.23 1067.77,1720 1715,1720 1819,1824 1819,2089 J12.3
PWM/OSCI: C8.1 J5.15 J5.16 J12.1 U1.8 X1.1 | length 2874.8
  Top Layer w7: X1.1 1003.23,1183.77 1003.23,1162.77 1014,1152 1040.4,1152 1073.19,1184.79 1073.3,1184.79 1078.99,1190.47 U1.8
  Top Layer w10: J5.16 466.5,1796.5 v1(703,1560) 878.35,1384.65 878.35,1286.69 893.03,1272 C8.1 895,1235 938,1192 X1.1
  Bottom Layer w10: v1(703,1560) 860.04,1560 1638.04,2338 1774,2338 J12.1
PWM/OSCO: C9.1 J5.17 J5.18 J11.1 U1.9 X1.2 | length 3456.4
  Top Layer w7: C9.1 895,1048 939,1092 X1.2 1003.23,1100.23 1003.23,1125.23 1013,1135 1047.04,1135 ; 1079.83,1167.79 1047.04,1135 ; U1.9 1082.83,1170.79 1047.04,1135
  Top Layer w10: J5.18 488.5,1696.5 v1(648,1537) 646.09,1535.09 646.09,1528.02 645,1526.93 645,1043.08 716.08,972 850,972 C9.1
  Bottom Layer w7: X1.2 X1.2@1005,1092
  Bottom Layer w10: v1(648,1537) 723,1612 888,1612 1631,2355 1869,2355 J11.1
RESET: J4.3 J5.19 J5.20 K1.2 R9.1 U1.10 | length 4739.9
  Top Layer w10: J5.20@124,1598 224,1598 424,1398 J4.3 427,1391 443,1391 625,1209 625,1039.04 722.04,942 920.39,942 1040,1061.61 1040,1106.04 1085.06,1151.1 U1.10 ; K1.2 1485.96,144.93 1516,174.97 1516,220 1536,200 1536,195 1578,153 v1(1578,128)
  Bottom Layer w10: J5.20 24,1496.5 24,237.1 135.1,126 1377.53,126 1379.53,128 v1(1578,128)
RX: R5.1 U3.3 | length 560.3
  Top Layer w10: R5.1 2068.19,3207.14 2203.14,3207.14 2236,3240 2455,3240 2497,3282 U3.3
RX0: J6.19 J6.20 J8.8 U1.39 | length 2973.9
  Top Layer w10: U1.39 1410.9,1461.9 1447.07,1498.07 1715,1500.88 1715.12,1501 1730,1501 1730.09,1500.91 1748.09,1500.91 v1(1750,1499) ; v1(1750,939.06) 1748.09,937.14 1748.09,605.91 2160,194 J8.8 ; v1@1750,1499.07 2224.03,1505.61 2433.11,1505.61 2522.36,1594.86 J6.20 ; J6.20@2524,1598 2622.5,1598 J6.19
  Bottom Layer w10: v1(1750,939.06) v1(1750,1499) ; J6.19 J6.19@2625.5,1596.5
SCK: J3.5 J5.37 J5.38 U1.19 | length 3442.3
  Top Layer w7: U1.19@1351.84,1017.17 U1.19
  Top Layer w10: J5.38@124,698 224,698 271,745 477,745 717,505 1286,505 1351,570 v1(1351,602) 1351.84,602.84 U1.19@1351.84,1017.17
  Bottom Layer w10: J5.37@224,698 J5.37@228,698 ; v1(1351,602) 1352.91,603.91 1559.95,603.91 1927,970.96 1927,1355 2126,1554 J3.5
SCL: J3.1 J5.5 J5.6 U1.3 | length 3012
  Top Layer w10: J5.6@124,2298 224,2298 225.5,2296.5 465.5,2296.5 v2(1086,1676) ; v2@1093.33,1676 1093.33,1321.95 1126.26,1289.02 1164.71,1289.02 U1.3
  Bottom Layer w10: v2(1086,1676) 2046,1676 J3.1
SDA: J3.2 J5.7 J5.8 U1.4 | length 2993
  Top Layer w10: J5.8@124,2198 J5.7@224,2198 ; J5.7 330,2196.5 360.5,2227 476,2227 1074,1629 v2@1074,1627.82 ; v2@1072,1627.82 v2(1066.33,1627.82) 1066.33,1324.91 1121.9,1269.33 1164.71,1269.33 U1.4
  Bottom Layer w10: v2(1066.33,1627.82) 2097.82,1627.82 J3.2
TX: D1.2 R4.1 U3.2 | length 892
  Top Layer w10: D1.2 1872,3101 1908,3065 2026,3065 2063,3102 R4.1 2124,3102 2245,3223 2500,3223 2547,3270 U3.2
TX0: J6.17 J6.18 J8.7 U1.40 | length 3001.8
  Top Layer w7: U1.40 1391.21,1469.21 1448,1526
  Top Layer w10: 1448,1526 v1(1768,1526) 2194,1526 2273,1605 2432.5,1605 J6.18 J6.17 ; v1(1772,917) 1772,606.04 2084.04,294 J8.7
  Bottom Layer w10: v1(1768,1526) 1769.91,1524.09 1769.91,1510.2 1772,1508.11 v1(1772,917)
USB_D+: R2.2 U3.5 | length 394.8
  Top Layer w10: R2.2 2073,3418 2115,3460 2346.78,3460 2397,3409.78 U3.5
USB_D-: R3.2 U3.6 | length 392.2
  Top Layer w10: R3.2 2073,3312.67 2093,3332.67 2093,3365.97 2168.03,3441 2315.78,3441 2347,3409.78 U3.6
VIN: PTC1.1 USB1.A4 USB1.A9 USB1.B4 USB1.B9 | length 511.6
  Top Layer w20: 220,3160 223,3160 223,3128 239,3112 389,3112 412,3135 412,3161.41 412.59,3162 ; 412,3211.5 412,3234 464,3286 532.5,3286 583.5,3235 PTC1.1
~D3: J5.43 J5.44 J8.5 U1.22 | length 2973.9
  Top Layer w7: 388,443 473,443 ; U1.22@1410.9,1024.9 U1.22
  Top Layer w10: J5.44@124,398 343,398 388,443 ; 473,443 619,297 1318,297 v1(1516,495) 1515,496 1515,867 1410.9,971.1 U1.22@1410.9,1024.9 ; J8.5@2303,494 J8.5
  Bottom Layer w10: v1(1516,495) 1516.5,494.5 2323.5,494.5 J8.5
~D5: J8.3 J11.2 | length 2060.2
  Top Layer w10: J8.3 J8.3@2338,694
  Bottom Layer w10: J11.2 2340.96,2191 2415,2116.96 2415,1071.97 2248.19,905.16 2248.19,752.53 2290,710.71 2291.05,710.71 2307.76,694 J8.3
~D6: J8.2 J12.2 | length 2083.4
  Top Layer w10: J8.2@2293,794 J8.2
  Bottom Layer w10: J12.2 1825.47,2195.47 1871,2195.47 1913.53,2238 2318,2238 2432,2124 2432,902 J8.2
~D9: J3.9 J5.21 J5.22 U1.11 | length 3355.2
  Top Layer w10: J5.22@124,1498 224,1498 J5.21@224,1496.61 ; J5.21 231.51,1488.99 260.13,1488.99 406.11,1343 449,1343 598,1194 598,1042 718,922 930,922 1065,1057 v1(1065,1062) 1065,1107 1090,1132 1137.98,1132 1138.88,1131.1 1164.52,1131.1 U1.11 ; v1(1513,992) 1621.83,883.17 1621.83,586.59 v1(1621.12,585.88)
  Bottom Layer w10: v1(1065,1062) 1135,992 v1(1513,992) ; v1(1621.12,585.88) 1640.21,604.98 1640.21,609.21 2185,1154 J3.9
~D10: J3.8 J5.39 J5.40 U1.20 | length 3311.3
  Top Layer w7: 269,643 450,643
  Top Layer w10: J5.40@124,598 224,598 269,643 ; 450,643 540.72,643 841.72,342 1308,342 1429,463 v1(1429,500) 1429,893 1371.53,950.47 U1.20
  Bottom Layer w10: v1(1429,500) 1430.91,498.09 1451.75,498.09 1451.92,497.92 1488.14,497.92 1494,503.77 1494,504.11 1506.89,517 1521.12,517 2258.12,1254 J3.8
~D11: J5.41 J5.42 J10.1 U1.21 | length 4089.4
  Top Layer w7: 395.7,543 454,543 ; 1391.21,1001.81 U1.21
  Top Layer w10: J5.42@124,498 350.7,498 395.7,543 ; 454,543 675,322 1312.04,322 1469,478.96 1469,883 1391.21,960.79 1391.21,1001.81 ; v1(1649,1768) 1693,1768 v1(1860,1601)
  Bottom Layer w10: v1(1470,665) 1551.11,665 1860,973.89 v1(1860,1601) ; v1(1649,1768) 1649,1880.03 1651,1882.03 1651,2233 J10.1
~D11/MOSI: J3.7 J10.2 | length 1425.4
  Bottom Layer w10: J10.2 1761,2139 2130,2139 2255.79,2013.21 2351.76,2013.21 2398,1966.97 2398,1428 J3.7
pads on no net: J3.3 J4.1 K1. K1.3 K1.4 U3.7 U3.8 U3.9 U3.10 U3.11 U3.12 U3.13 U3.14 U3.15 USB1.A5 USB1.A8 USB1.B5 USB1.B8

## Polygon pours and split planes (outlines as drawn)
GND on Top Layer "NONET_L-01_P-001" (hatched 45Degree grid 20 track 8, remove dead copper, pour order 0): 2949,-163 2949,2923 -165,2923 -165,-163
GND on Top Layer "NONET_L-01_P-001" (hatched 45Degree grid 20 track 8, remove dead copper, pour order 1): 2949,3097 2949,3550 -165,3550 -165,3097
GND on Bottom Layer "NONET_L-01_P-001" (hatched 45Degree grid 20 track 8, remove dead copper, pour order 4): -165,-162 -165,2923 2949,2923 2949,-162
GND on Bottom Layer "NONET_L-01_P-001" (hatched 45Degree grid 20 track 8, remove dead copper, pour order 2): -165,3097 -165,3552 2949,3552 2949,3097

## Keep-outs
Keep-Out Layer:
  circle w5: c1720.69,92.43 r64.72
  circle w5: c1720.69,92.43 r64.72
  circle w5: c420.69,2142.43 r64.72
  circle w5: c2320.69,2092.43 r64.72
  circle w5: c131.69,2838.43 r64.72
  circle w5: c2320.69,2557.43 r64.72
  circle w5: c1142,3010 r31
  circle w5: c1242,3010 r31
  circle w5: c1342,3010 r31
  circle w5: c1442,3010 r31
  circle w5: c1542,3010 r31
  lines w5: -5.68,153.05 ccw(c73.06,153.05) 73.06,74.31 447.07,74.31 527.39,-6 1240.4,-6 1260.4,14 1310,14 1310,38 1343,38 1464,38 ; -5.69,154 -5.69,2899.31 ; -5.69,2894.94 cw(c73.06,2894.94) 73.06,2973.69 550.79,2973.69 ; 73.22,3046.15 550.95,3046.15 cw(c550.95,3028) 569.1,3028 569.1,2992 cw(c550.95,2992) 550.95,2973.85 ; 73.35,3046.15 cw(c73.35,3124.89) -5.39,3124.89 -5.39,3401.48 cw(c73.35,3401.48) 73.35,3480.22 134.78,3480.22 135,3480 135,3420 495,3420 495,3479.12 2671.95,3479.12 cw(c2671.95,3400.93) 2750.14,3400.93 2750.14,3124.34 cw(c2671.95,3124.34) 2671.95,3046.15 2133.15,3046.15 ccw(c2133.15,3028) 2115,3028 2115,2992 ccw(c2133.15,2992) 2133.15,2973.85 2671.95,2973.85 ; 643.15,2973.69 1036.85,2973.69 ; 643.15,2973.85 cw(c643.15,2992) 625,2992 625,3028 cw(c643.15,3028) 643.15,3046.15 1036.85,3046.15 cw(c1036.85,3028) 1055,3028 1055,2992 cw(c1036.85,2992) 1036.85,2973.85 ; 1344,38 1464,38 ; 1497,13.73 1497,38 1464,38 ; 1497.36,13.73 1546.96,13.73 1566.96,-6.27 ; 1566.96,-6 1823.45,-6 ; 1647.15,2973.69 2040,2973.69 ; 1647.15,2973.85 cw(c1647.15,2992) 1629,2992 1629,3028 cw(c1647.15,3028) 1647.15,3046.15 2040.85,3046.15 cw(c2040.85,3028) 2059,3028 2059,2992 cw(c2040.85,2992) 2040.85,2973.85 ; 1825.02,-4.43 1868.45,39 ; 1888.45,59 1823.45,-6 ; 2672.03,2973.77 cw(c2672.03,2895.58) 2750.22,2895.58 2750.22,153.05 cw(c2671.48,153.06) 2671.48,74.31 1903.76,74.31 1823.45,-6

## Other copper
Top Layer:
  rectangle net VIN: 398,3150 422,3179
  region net GND: 1301,747 1301,826 1173,826 1173,747
  rectangle net VIN: 209,3150 233,3179
  rectangle net VIN: 398,3195 422,3224
  pour cut-out: 1289.5,141 1512.5,141 1512.5,27 1511.5,28 1290.5,28
Bottom Layer:
  pour cut-out: 1290.5,140 1513.5,140 1513.5,26 1512.5,27 1291.5,27

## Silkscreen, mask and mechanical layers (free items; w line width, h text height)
Top Overlay:
  drawing of 25 lines, arcs and shapes, not listed
  text "3.3V" at 1213.78,3155.95 h50 r90
  text "RX" at 1307.99,3155.95 h50 r90
  text "VSS" at 1407.99,3156 h50 r90
  text "TX" at 1507.99,3155.95 h50 r90
  text "RUN" at 1586,3092.67 h60
  text "5V" at 760,2791.29 h50
  text "VDD" at 831.05,2779.01 h50
  text "DIO" at 1304,2776 h50 r90
  text "CLK" at 1504,2766 h50 r90
  text "VDD" at 1194,2761 h50 r90
  text "VSS" at 1404,2761 h50 r90
  text "3.3V" at 723,2728.22 h50
  text "P02" at 281,2481.54 h46
  text "P01" at 2399,2481.54 h46
  text "1" at 50.42,2480 h50
  text "48" at 2691.06,2480.28 h50
  text "P03" at 281,2387.54 h46
  text "P00" at 2399,2387.54 h46
  text "2" at 40.95,2386 h50
  text "47" at 2691.06,2386.07 h50
  text "P04" at 281,2278.26 h46
  text "P27" at 2399,2278.01 h46
  text "3" at 41.27,2277 h50
  text "46" at 2691.06,2277 h50
  text "P05" at 281,2176.47 h46
  text "P26" at 2399,2176.47 h46
  text "4" at 40.02,2175 h50
  text "45" at 2691.06,2175.28 h50
  text "Function Select" at 1179,2096.05 h60
  text "P06" at 281,2081.99 h46
  text "P25" at 2399,2081.99 h46
  text "5" at 40.99,2081 h50
  text "44" at 2691.06,2080.51 h50
  text "MOSI" at 1422.01,2053.01 h50
  text "~D11" at 1541,2042.95 h50
  text "PWM" at 1426.54,1996.01 h50
  text "P07" at 281,1981.99 h46
  text "P24" at 2399,1981.73 h46
  text "6" at 41.04,1980.72 h50
  text "43" at 2691.06,1980.72 h50
  text "OSCI/PWM" at 1303.6,1936.01 h50
  text "D15/SCL" at 2070.86,1932 h50
  text "~D6" at 1541,1925.22 h50
  text "VSS" at 281.04,1881.8 h46
  text "P23" at 2399,1881.99 h46
  text "7" at 41.5,1880.72 h50
  text "42" at 2691.06,1880.45 h50
  text "P55" at 1454.63,1872.29 h50
  text "D14/SDA" at 2064.27,1837 h50
  text "OSCI/PWM" at 1303.6,1817.01 h50
  text "~D5" at 1541,1809.29 h50
  text "P50" at 281,1781.26 h46
  text "P22" at 2399,1781.01 h46
  text "8" at 41.13,1780 h50
  text "41" at 2691.06,1779.72 h50
  text "P54" at 1455,1755.29 h50
  text "NC" at 2187.93,1737 h50
  text "P51" at 281,1676.26 h46
  text "P21" at 2399,1676.01 h46
  text "9" at 41.18,1675 h50
  text "40" at 2691.06,1675 h50
  text "GND" at 2152.74,1639 h50
  text "P52" at 281,1579.26 h46
  text "P20" at 2399,1579.26 h46
  text "10" at 19.46,1578 h50
  text "39" at 2691.06,1578 h50
  text "SCK/D13" at 2064.36,1534 h50
  text "IOREF" at 485,1479 h50
  text "P53" at 281,1476.54 h46
  text "P17" at 2399,1476.29 h46
  text "11" at 25.56,1475 h50
  text "38" at 2691.06,1475.28 h50
  text "MISO/D12" at 2043.92,1434 h50
  text "RESET" at 485,1385 h50
  text "P54" at 281,1382.6 h46
  text "P16" at 2399,1382.54 h46
  text "12" at 19.69,1381 h50
  text "37" at 2691.06,1381.28 h50
  text "MOSI/~D11" at 2018.2,1337 h50
  text "3.3V" at 485,1284 h50
  text "P55" at 281,1278.33 h46
  text "P15" at 2399,1278.26 h46
  text "13" at 19.37,1277 h50
  text "36" at 2691.06,1277 h50
  text "~D10" at 2143.18,1229 h50
  text "P47" at 281,1179.35 h46
  text "5V" at 485,1179 h50
  text "P14" at 2399,1179.29 h46
  text "14" at 19.51,1178 h50
  text "35" at 2691.06,1178.28 h50
  text "~D9" at 2167.87,1134 h50
  text "GND" at 485,1079 h50
  text "P46" at 281,1076.26 h46
  text "P13" at 2399,1076.26 h46
  text "15" at 19.14,1075 h50
  text "34" at 2691.06,1075 h50
  text "D8" at 2195.59,1039 h50
  text "VDD" at 281.04,980.07 h46
  text "P12" at 2399,980.01 h46
  text "16" at 19.37,979 h50
  text "GND" at 485,979 h50
  text "33" at 2691.06,979 h50
  text "P45" at 281,882.6 h46
  text "P11" at 2399,882.29 h46
  text "17" at 19.37,881 h50
  text "32" at 2691.06,881.28 h50
  text "VIN" at 485.06,879 h50
  text "D7" at 2195.69,879 h50
  text "P44" at 281,780.07 h46
  text "P10" at 2399,780.26 h46
  text "18" at 19.33,779 h50
  text "~D6" at 2167.97,779 h50
  text "31" at 2691.06,779 h50
  text "P43" at 281,686.26 h46
  text "P30" at 2399,686.26 h46
  text "19" at 19.33,685 h50
  text "30" at 2691.06,685 h50
  text "A0" at 494,679 h50
  text "~D5" at 2167.72,679 h50
  text "P42" at 281,583.01 h46
  text "P31" at 2399,583.26 h46
  text "20" at 15.86,582 h50
  text "29" at 2691,582 h50
  text "A1" at 494,579 h50
  text "D4" at 2195.78,577 h50
  text "NBK1220" at 1163,510 h120
  text "A2" at 494,479 h50
  text "P32" at 2399,478.54 h46
  text "P41" at 281,478.29 h46
  text "21" at 21.96,477 h50
  text "28" at 2691,477.28 h50
  text "~D3" at 2167.97,474 h50
  text "2022-07-07   MB0029" at 908.8,401 h100
  text "A3" at 494,379 h50
  text "P40" at 281,377.54 h46
  text "P33" at 2399,377.54 h46
  text "22" at 16.09,376 h50
  text "27" at 2691,376 h50
  text "D2" at 2195.98,374 h50
  text "TX0/D1" at 2101.26,292 h50
  text "23" at 15.77,284 h50
  text "P37" at 281,281.99 h46
  text "P34" at 2399,281.99 h46
  text "A4" at 494,279 h50
  text "26" at 2691,270 h50
  text "RX0/D0" at 2096.28,197 h50
  text "A5" at 494,184 h50
  text "24" at 15.91,183 h50
  text "25" at 2691,183.28 h50
  text "P36" at 281,181.99 h46
  text "P35" at 2399,181.99 h46
  text "Reset Key" at 939,99.15 h70
Bottom Overlay:
  text "P02" at 85,2481.54 h46
  text "P01" at 2730,2481.54 h46
  text "1" at 297.58,2480 h50
  text "48" at 2456.94,2480.28 h50
  text "P03" at 85,2387.54 h46
  text "P00" at 2730,2387.54 h46
  text "2" at 307.05,2386 h50
  text "47" at 2456.94,2386.07 h50
  text "P04" at 85,2278.26 h46
  text "P27" at 2730,2278.01 h46
  text "3" at 306.73,2277 h50
  text "46" at 2456.94,2277 h50
  text "P05" at 85,2176.47 h46
  text "P26" at 2730,2176.47 h46
  text "4" at 307.98,2175 h50
  text "45" at 2456.94,2175.28 h50
  text "P06" at 85,2081.99 h46
  text "P25" at 2730,2081.99 h46
  text "5" at 307.01,2081 h50
  text "44" at 2456.94,2080.51 h50
  text "P07" at 85,1981.99 h46
  text "P24" at 2730,1981.73 h46
  text "6" at 306.96,1980.72 h50
  text "43" at 2456.94,1980.72 h50
  text "VSS" at 84.96,1883.7 h40
  text "P23" at 2730,1881.99 h46
  text "7" at 306.5,1880.72 h50
  text "42" at 2456.94,1880.45 h50
  text "P50" at 85,1781.26 h46
  text "P22" at 2730,1781.01 h46
  text "8" at 306.87,1780 h50
  text "41" at 2456.94,1779.72 h50
  text "P51" at 85,1676.26 h46
  text "P21" at 2730,1676.01 h46
  text "9" at 306.82,1675 h50
  text "40" at 2456.94,1675 h50
  text "P52" at 85,1579.26 h46
  text "P20" at 2730,1579.26 h46
  text "10" at 328.54,1578 h50
  text "39" at 2456.94,1578 h50
  text "P53" at 85,1476.54 h46
  text "P17" at 2730,1476.29 h46
  text "11" at 322.44,1475 h50
  text "38" at 2456.94,1475.28 h50
  text "P54" at 85,1382.6 h46
  text "P16" at 2730,1382.54 h46
  text "12" at 328.31,1381 h50
  text "37" at 2456.94,1381.28 h50
  text "P55" at 85,1278.33 h46
  text "P15" at 2730,1278.26 h46
  text "13" at 328.63,1277 h50
  text "36" at 2456.94,1277 h50
  text "P47" at 85,1179.35 h46
  text "P14" at 2730,1179.29 h46
  text "14" at 328.49,1178 h50
  text "35" at 2456.94,1178.28 h50
  text "P46" at 85,1076.26 h46
  text "P13" at 2730,1076.26 h46
  text "15" at 328.86,1075 h50
  text "34" at 2456.94,1075 h50
  text "VDD" at 84.96,981.98 h40
  text "P12" at 2730,980.01 h46
  text "16" at 328.63,979 h50
  text "33" at 2456.94,979 h50
  text "P45" at 85,882.6 h46
  text "P11" at 2730,882.29 h46
  text "17" at 328.63,881 h50
  text "32" at 2456.94,881.28 h50
  text "P44" at 85,780.07 h46
  text "P10" at 2730,780.26 h46
  text "18" at 328.67,779 h50
  text "31" at 2456.94,779 h50
  text "P43" at 85,686.26 h46
  text "P30" at 2730,686.26 h46
  text "19" at 328.67,685 h50
  text "30" at 2456.94,685 h50
  text "P42" at 85,583.01 h46
  text "P31" at 2730,583.26 h46
  text "20" at 332.14,582 h50
  text "29" at 2457,582 h50
  text "P32" at 2730,478.54 h46
  text "P41" at 85,478.29 h46
  text "21" at 326.04,477 h50
  text "28" at 2457,477.28 h50
  text "P40" at 85,377.54 h46
  text "P33" at 2730,377.54 h46
  text "22" at 331.91,376 h50
  text "27" at 2457,376 h50
  text "23" at 332.23,284 h50
  text "P37" at 85,281.99 h46
  text "P34" at 2730,281.99 h46
  text "26" at 2457,270 h50
  text "24" at 332.09,183 h50
  text "25" at 2457,183.28 h50
  text "P36" at 85,181.99 h46
  text "P35" at 2730,181.99 h46
Mechanical 1:
  circle w5: c1542,3010 r31
  circle w5: c1442,3010 r31
  circle w5: c1342,3010 r31
  circle w5: c1242,3010 r31
  circle w5: c1142,3010 r31
  circle w5: c2320.69,2557.43 r64.72
  circle w5: c131.69,2838.43 r64.72
  circle w5: c2320.69,2092.43 r64.72
  circle w5: c420.69,2142.43 r64.72
  circle w5: c1720.69,92.43 r64.72
  circle w5: c1720.69,92.43 r64.72
  lines w5: -5.68,153.05 ccw(c73.06,153.05) 73.06,74.31 447.07,74.31 527.39,-6 1240.4,-6 1260.4,14 1310,14 1310,38 1343,38 1464,38 ; -5.69,154 -5.69,2899.31 ; -5.69,2894.94 cw(c73.06,2894.94) 73.06,2973.69 550.79,2973.69 ; 73.22,3046.15 550.95,3046.15 cw(c550.95,3028) 569.1,3028 569.1,2992 cw(c550.95,2992) 550.95,2973.85 ; 73.35,3046.15 cw(c73.35,3124.89) -5.39,3124.89 -5.39,3401.48 cw(c73.35,3401.48) 73.35,3480.22 134.78,3480.22 135,3480 135,3420 495,3420 495,3479.12 2671.95,3479.12 cw(c2671.95,3400.93) 2750.14,3400.93 2750.14,3124.34 cw(c2671.95,3124.34) 2671.95,3046.15 2133.15,3046.15 ccw(c2133.15,3028) 2115,3028 2115,2992 ccw(c2133.15,2992) 2133.15,2973.85 2671.95,2973.85 ; 643.15,2973.69 1036.85,2973.69 ; 643.15,2973.85 cw(c643.15,2992) 625,2992 625,3028 cw(c643.15,3028) 643.15,3046.15 1036.85,3046.15 cw(c1036.85,3028) 1055,3028 1055,2992 cw(c1036.85,2992) 1036.85,2973.85 ; 1344,38 1464,38 ; 1497,13.73 1497,38 1464,38 ; 1497.36,13.73 1546.96,13.73 1566.96,-6.27 ; 1566.96,-6 1823.45,-6 ; 1647.15,2973.69 2040,2973.69 ; 1647.15,2973.85 cw(c1647.15,2992) 1629,2992 1629,3028 cw(c1647.15,3028) 1647.15,3046.15 2040.85,3046.15 cw(c2040.85,3028) 2059,3028 2059,2992 cw(c2040.85,2992) 2040.85,2973.85 ; 1825.02,-4.43 1868.45,39 ; 1888.45,59 1823.45,-6 ; 2672.03,2973.77 cw(c2672.03,2895.58) 2750.22,2895.58 2750.22,153.05 cw(c2671.48,153.06) 2671.48,74.31 1903.76,74.31 1823.45,-6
